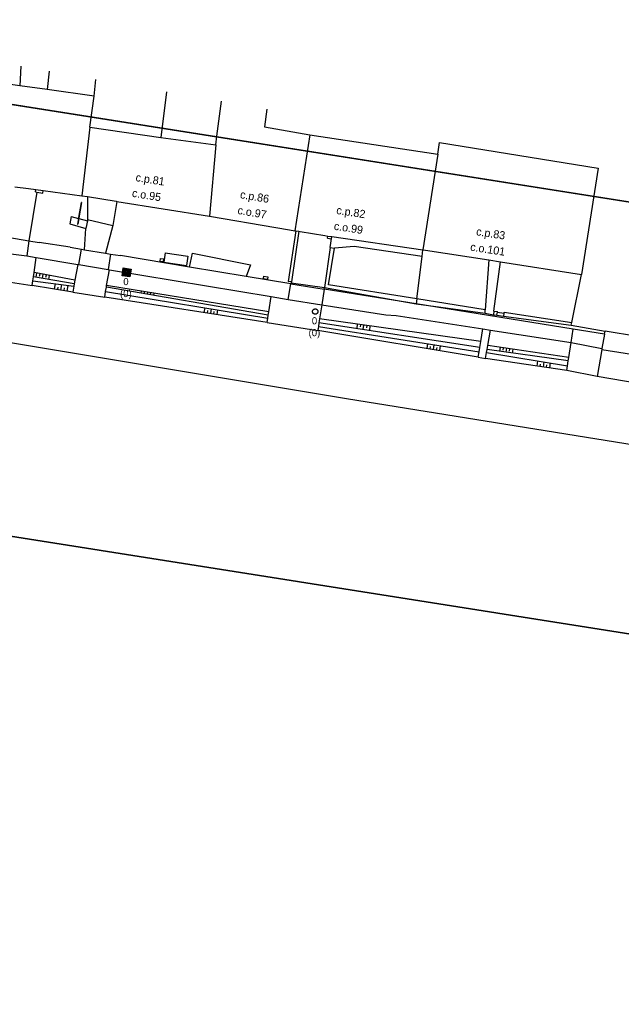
# Model space of a CAD drawing. Extents: x -594451 to -591069, y -1167621 to -1167156.
# Drawn here: x -591351.9 to -591295.5, y -1167315.7 to -1167223.5 of the extents above; entities that cross this region are included whole.
import ezdxf

# ---------------------------------------------------------------- set-up
doc = ezdxf.new("R2010")
doc.units = 0
for name, color, linetype in [('MAPA', 7, 'Continuous'), ('Uliční vpusť', 7, 'Continuous'), ('Vstupní šachta stoky', 7, 'Continuous'), ('Žádosti', 7, 'Continuous')]:
    doc.layers.add(name, color=color, linetype=linetype)

msp = doc.modelspace()

# ---------------------------------------------------------------- linework, layer by layer
at = {"layer": 'MAPA'}
for p, q in [((-591351.764, -1167227.873), (-591351.87, -1167229.7)), ((-591349.119, -1167228.334), (-591349.29, -1167230.06)), ((-591344.89, -1167230.68), (-591344.72, -1167229.1)), ((-591338.114, -1167230.25), (-591338.62, -1167234.53)), ((-591333.39, -1167234.43), (-591332.95, -1167231.149)), ((-591328.705, -1167231.889), (-591328.9, -1167233.54))]:
    msp.add_line(p, q, dxfattribs=at)
for points in [[(-591349.29, -1167230.06), (-591351.87, -1167229.7), (-591357.18, -1167228.96)], [(-591344.89, -1167230.68), (-591349.29, -1167230.06)], [(-591345.3, -1167233.59), (-591344.89, -1167230.68)], [(-591345.3, -1167233.59), (-591346.03, -1167240.01)], [(-591345.3, -1167233.59), (-591338.62, -1167234.53)], [(-591328.9, -1167233.54), (-591324.66, -1167234.28)], [(-591338.62, -1167234.53), (-591333.47, -1167235.24)], [(-591333.47, -1167235.24), (-591333.39, -1167234.43)], [(-591324.66, -1167234.28), (-591326.07, -1167243.28)], [(-591324.66, -1167234.28), (-591312.67, -1167236.1)], [(-591312.67, -1167236.1), (-591312.5, -1167235.01)], [(-591312.5, -1167235.01), (-591297.62, -1167237.41)], [(-591333.47, -1167235.24), (-591334.07, -1167241.92)], [(-591312.67, -1167236.1), (-591314.06, -1167245.06)], [(-591297.62, -1167237.41), (-591299.19, -1167247.38)], [(-591352.32, -1167239.17), (-591351.04, -1167239.34)], [(-591351.04, -1167239.34), (-591350.37, -1167239.43), (-591349.67, -1167239.52), (-591346.03, -1167240.01)], [(-591350.27, -1167239.67), (-591351.01, -1167244.23)], [(-591350.4, -1167239.65), (-591350.37, -1167239.43)], [(-591350.4, -1167239.65), (-591350.27, -1167239.67), (-591349.7, -1167239.75)], [(-591349.7, -1167239.75), (-591349.67, -1167239.52)], [(-591346.07, -1167240.64), (-591346.11, -1167240.63), (-591346.36, -1167242.05), (-591346.37, -1167242.13)], [(-591346.07, -1167240.64), (-591346.32, -1167242.06)], [(-591346.03, -1167240.01), (-591345.52, -1167240.09)], [(-591345.5, -1167240.09), (-591345.52, -1167242.23), (-591345.52, -1167242.36)], [(-591345.52, -1167240.09), (-591345.5, -1167240.09), (-591342.83, -1167240.52)], [(-591342.75, -1167240.53), (-591343.13, -1167242.79)], [(-591342.83, -1167240.52), (-591342.75, -1167240.53), (-591334.07, -1167241.92)], [(-591347.03, -1167241.95), (-591347.18, -1167242.65)], [(-591347.03, -1167241.95), (-591346.37, -1167242.13)], [(-591346.37, -1167242.13), (-591346.45, -1167242.66), (-591346.41, -1167242.67)], [(-591346.33, -1167242.14), (-591346.41, -1167242.67)], [(-591346.32, -1167242.06), (-591346.33, -1167242.14)], [(-591346.33, -1167242.14), (-591345.52, -1167242.36)], [(-591345.52, -1167242.36), (-591345.67, -1167243.07)], [(-591345.52, -1167242.23), (-591343.13, -1167242.79)], [(-591334.07, -1167241.92), (-591327.84, -1167242.98)], [(-591347.18, -1167242.65), (-591345.67, -1167243.07)], [(-591345.78, -1167245.06), (-591345.67, -1167243.07)], [(-591343.13, -1167242.79), (-591343.83, -1167245.4)], [(-591327.84, -1167242.98), (-591326.57, -1167243.19)], [(-591325.99, -1167243.29), (-591326.7, -1167248.03)], [(-591326.57, -1167243.19), (-591326.07, -1167243.28)], [(-591325.69, -1167243.34), (-591326.38, -1167248.08)], [(-591326.07, -1167243.28), (-591325.99, -1167243.29), (-591325.69, -1167243.34), (-591325.56, -1167243.36)], [(-591325.56, -1167243.36), (-591323.27, -1167243.73)], [(-591353.71, -1167243.77), (-591351.01, -1167244.23)], [(-591351.01, -1167244.23), (-591351.21, -1167245.65)], [(-591351.01, -1167244.23), (-591350.05, -1167244.39)], [(-591323.27, -1167243.73), (-591322.98, -1167243.78), (-591322.61, -1167243.84), (-591322.6, -1167243.84)], [(-591323.02, -1167243.99), (-591322.98, -1167243.78)], [(-591323.02, -1167243.99), (-591322.64, -1167244.03)], [(-591322.75, -1167244.85), (-591322.6, -1167243.84)], [(-591322.64, -1167244.03), (-591322.61, -1167243.84)], [(-591322.6, -1167243.84), (-591314.06, -1167245.06)], [(-591347.13, -1167244.84), (-591350.05, -1167244.39)], [(-591347.13, -1167244.84), (-591346.08, -1167245.01)], [(-591346.32, -1167246.46), (-591346.08, -1167245.01)], [(-591346.08, -1167245.01), (-591345.78, -1167245.06)], [(-591345.78, -1167245.06), (-591343.83, -1167245.4)], [(-591322.75, -1167244.85), (-591323.3, -1167248.62)], [(-591314.64, -1167249.67), (-591322.9, -1167248.34), (-591322.35, -1167244.92)], [(-591322.75, -1167244.85), (-591322.35, -1167244.92)], [(-591314.14, -1167245.69), (-591320.52, -1167244.75), (-591322.35, -1167244.92)], [(-591314.64, -1167249.67), (-591314.14, -1167245.69), (-591314.06, -1167245.06)], [(-591314.06, -1167245.06), (-591313.81, -1167245.1)], [(-591313.81, -1167245.1), (-591307.89, -1167246.02)], [(-591353.94, -1167245.3), (-591351.21, -1167245.65)], [(-591351.21, -1167245.65), (-591350.31, -1167245.8)], [(-591350.69, -1167248.41), (-591350.63, -1167247.99), (-591350.57, -1167247.61), (-591350.51, -1167247.21), (-591350.31, -1167245.8)], [(-591350.31, -1167245.8), (-591346.43, -1167246.44)], [(-591343.83, -1167245.4), (-591343.34, -1167245.48)], [(-591343.34, -1167245.48), (-591343.58, -1167246.92)], [(-591343.34, -1167245.48), (-591342.42, -1167245.61)], [(-591326.45, -1167248.27), (-591330.64, -1167247.57), (-591335.95, -1167246.69), (-591342.42, -1167245.61)], [(-591338.7, -1167246.13), (-591338.66, -1167245.89)], [(-591338.7, -1167246.13), (-591338.38, -1167246.18)], [(-591338.66, -1167245.89), (-591338.34, -1167245.93)], [(-591338.38, -1167246.18), (-591338.34, -1167245.93)], [(-591338.24, -1167245.36), (-591338.36, -1167246.22)], [(-591338.24, -1167245.36), (-591336.1, -1167245.67)], [(-591336.1, -1167245.67), (-591336.23, -1167246.53)], [(-591335.95, -1167246.69), (-591335.67, -1167245.39), (-591330.24, -1167246.48), (-591330.64, -1167247.57)], [(-591307.89, -1167246.02), (-591308.21, -1167250.7)], [(-591307.89, -1167246.02), (-591306.79, -1167246.19)], [(-591307.4, -1167250.82), (-591306.79, -1167246.19)], [(-591306.79, -1167246.19), (-591299.19, -1167247.38)], [(-591346.43, -1167246.44), (-591346.69, -1167247.91), (-591346.75, -1167248.25), (-591346.79, -1167248.48), (-591346.88, -1167249.03)], [(-591346.43, -1167246.44), (-591346.32, -1167246.46), (-591343.58, -1167246.92), (-591343.46, -1167246.94)], [(-591343.9, -1167249.51), (-591343.81, -1167248.98), (-591343.74, -1167248.57), (-591343.72, -1167248.43), (-591343.46, -1167246.94)], [(-591343.46, -1167246.94), (-591328.28, -1167249.46)], [(-591338.36, -1167246.22), (-591336.23, -1167246.53)], [(-591354.38, -1167247.85), (-591350.69, -1167248.41)], [(-591350.63, -1167247.99), (-591346.79, -1167248.48)], [(-591346.75, -1167248.25), (-591350.57, -1167247.61)], [(-591346.69, -1167247.91), (-591350.51, -1167247.21)], [(-591350.33, -1167247.65), (-591350.26, -1167247.26)], [(-591350, -1167247.53), (-591349.96, -1167247.31)], [(-591349.74, -1167247.75), (-591349.67, -1167247.36)], [(-591349.41, -1167247.63), (-591349.37, -1167247.42)], [(-591349.14, -1167247.85), (-591349.08, -1167247.47)], [(-591329, -1167247.53), (-591329.04, -1167247.76)], [(-591329.04, -1167247.76), (-591328.64, -1167247.83)], [(-591329, -1167247.53), (-591328.6, -1167247.6)], [(-591328.6, -1167247.6), (-591328.64, -1167247.83)], [(-591326.38, -1167248.08), (-591326.7, -1167248.03)], [(-591300.16, -1167252.14), (-591300.11, -1167251.89), (-591299.19, -1167247.38)], [(-591346.88, -1167249.03), (-591350.69, -1167248.41)], [(-591348.55, -1167248.25), (-591348.63, -1167248.74)], [(-591348.3, -1167248.57), (-591348.34, -1167248.79)], [(-591347.96, -1167248.33), (-591348.04, -1167248.84)], [(-591347.7, -1167248.65), (-591347.74, -1167248.89)], [(-591347.36, -1167248.41), (-591347.45, -1167248.94)], [(-591343.81, -1167248.98), (-591328.61, -1167251.49)], [(-591328.56, -1167251.2), (-591343.74, -1167248.57)], [(-591328.51, -1167250.89), (-591343.72, -1167248.43)], [(-591340.49, -1167249.14), (-591340.46, -1167248.96)], [(-591326.68, -1167249.73), (-591326.45, -1167248.27)], [(-591326.38, -1167248.08), (-591326.4, -1167248.16), (-591326.45, -1167248.27)], [(-591326.45, -1167248.27), (-591323.31, -1167248.76)], [(-591326.4, -1167248.16), (-591323.3, -1167248.62)], [(-591323.31, -1167248.76), (-591323.54, -1167250.22)], [(-591323.31, -1167248.76), (-591323.3, -1167248.62)], [(-591297.02, -1167252.99), (-591299.96, -1167252.52), (-591314.7, -1167250.14), (-591323.31, -1167248.76)], [(-591323.3, -1167248.62), (-591314.7, -1167250.14)], [(-591346.88, -1167249.03), (-591343.9, -1167249.51)], [(-591328.67, -1167251.89), (-591343.9, -1167249.51)], [(-591340.18, -1167249.09), (-591340.16, -1167249.01)], [(-591339.9, -1167249.24), (-591339.87, -1167249.05)], [(-591339.59, -1167249.2), (-591339.57, -1167249.1)], [(-591339.3, -1167249.34), (-591339.27, -1167249.15)], [(-591328.67, -1167251.89), (-591328.61, -1167251.49), (-591328.56, -1167251.2), (-591328.51, -1167250.89), (-591328.28, -1167249.46)], [(-591328.28, -1167249.46), (-591326.68, -1167249.73)], [(-591326.68, -1167249.73), (-591323.54, -1167250.22)], [(-591314.64, -1167249.67), (-591314.7, -1167250.14)], [(-591308.21, -1167250.7), (-591314.64, -1167249.67)], [(-591334.51, -1167250.51), (-591334.59, -1167250.95)], [(-591334.25, -1167250.77), (-591334.29, -1167251)], [(-591333.92, -1167250.61), (-591333.99, -1167251.05)], [(-591333.33, -1167250.71), (-591333.4, -1167251.14)], [(-591323.54, -1167250.22), (-591323.75, -1167251.54), (-591323.81, -1167251.91), (-591323.86, -1167252.25), (-591323.92, -1167252.63)], [(-591323.54, -1167250.22), (-591317.53, -1167251.17)], [(-591314.7, -1167250.14), (-591308.23, -1167251.02)], [(-591308.23, -1167251.02), (-591308.21, -1167250.7)], [(-591307.4, -1167250.82), (-591307.45, -1167251.16)], [(-591307.4, -1167250.82), (-591307.06, -1167250.85)], [(-591333.66, -1167250.85), (-591333.7, -1167251.1)], [(-591308.63, -1167253.68), (-591323.75, -1167251.54)], [(-591317.53, -1167251.17), (-591316.58, -1167251.23)], [(-591316.58, -1167251.23), (-591308.43, -1167252.49)], [(-591308.23, -1167251.02), (-591307.45, -1167251.16)], [(-591307.45, -1167251.16), (-591307.12, -1167251.2)], [(-591307.12, -1167251.2), (-591307.07, -1167250.91), (-591306.46, -1167251)], [(-591307.12, -1167251.2), (-591306.51, -1167251.28)], [(-591307.07, -1167250.91), (-591307.06, -1167250.85)], [(-591306.46, -1167251), (-591306.51, -1167251.28)], [(-591306.51, -1167251.28), (-591300.16, -1167252.14)], [(-591306.46, -1167251), (-591306.45, -1167250.93)], [(-591306.45, -1167250.93), (-591300.11, -1167251.89)], [(-591328.67, -1167251.89), (-591323.92, -1167252.63)], [(-591308.88, -1167255.12), (-591323.92, -1167252.63)], [(-591323.86, -1167252.25), (-591308.8, -1167254.65)], [(-591308.72, -1167254.22), (-591323.81, -1167251.91)], [(-591320.24, -1167252.46), (-591320.18, -1167252.04)], [(-591319.92, -1167252.3), (-591319.89, -1167252.09)], [(-591319.65, -1167252.55), (-591319.59, -1167252.13)], [(-591319.32, -1167252.39), (-591319.29, -1167252.17)], [(-591319.05, -1167252.64), (-591319, -1167252.21)], [(-591308.88, -1167255.12), (-591308.8, -1167254.65), (-591308.72, -1167254.22), (-591308.63, -1167253.68), (-591308.43, -1167252.49)], [(-591308.43, -1167252.49), (-591307.73, -1167252.6)], [(-591308.19, -1167255.26), (-591308.09, -1167254.69), (-591308.05, -1167254.43), (-591307.98, -1167254.03), (-591307.73, -1167252.6)], [(-591307.73, -1167252.6), (-591300.17, -1167253.77)], [(-591300.17, -1167253.77), (-591299.96, -1167252.52)], [(-591300.16, -1167252.14), (-591296.98, -1167252.69)], [(-591357.63, -1167252.95), (-591321.23, -1167259.02), (-591254.866, -1167269.682), (-591254.389, -1167269.757), (-591238.78, -1167272.23)], [(-591297.02, -1167252.99), (-591297.27, -1167254.32), (-591297.29, -1167254.42)], [(-591297.02, -1167252.99), (-591296.98, -1167252.69)], [(-591293.93, -1167253.2), (-591296.98, -1167252.69)], [(-591313.63, -1167253.88), (-591313.7, -1167254.32)], [(-591313.37, -1167254.15), (-591313.4, -1167254.37)], [(-591313.03, -1167253.98), (-591313.11, -1167254.42)], [(-591312.77, -1167254.23), (-591312.81, -1167254.47)], [(-591312.44, -1167254.07), (-591312.52, -1167254.52)], [(-591300.43, -1167255.48), (-591308.05, -1167254.43)], [(-591300.38, -1167255.17), (-591307.98, -1167254.03)], [(-591306.85, -1167254.6), (-591306.79, -1167254.21)], [(-591306.53, -1167254.47), (-591306.5, -1167254.26)], [(-591306.26, -1167254.68), (-591306.2, -1167254.3)], [(-591305.94, -1167254.56), (-591305.9, -1167254.34)], [(-591305.66, -1167254.76), (-591305.61, -1167254.39)], [(-591300.57, -1167256.38), (-591300.5, -1167255.94), (-591300.43, -1167255.48), (-591300.38, -1167255.17), (-591300.17, -1167253.77)], [(-591300.17, -1167253.77), (-591297.27, -1167254.32)], [(-591297.29, -1167254.42), (-591297.72, -1167256.94)], [(-591297.29, -1167254.42), (-591282.36, -1167256.75)], [(-591308.88, -1167255.12), (-591308.19, -1167255.26)], [(-591300.57, -1167256.38), (-591308.19, -1167255.26)], [(-591308.09, -1167254.69), (-591300.5, -1167255.94)], [(-591303.31, -1167255.48), (-591303.39, -1167255.97)], [(-591303.06, -1167255.79), (-591303.09, -1167256.01)], [(-591302.72, -1167255.57), (-591302.79, -1167256.06)], [(-591302.46, -1167255.86), (-591302.5, -1167256.1)], [(-591302.13, -1167255.67), (-591302.2, -1167256.14)], [(-591297.72, -1167256.94), (-591300.57, -1167256.38)], [(-591237.5, -1167266.94), (-591282.92, -1167259.49), (-591297.72, -1167256.94)]]:
    msp.add_lwpolyline(points, dxfattribs=at)
at = {"layer": 'Uliční vpusť'}
for points in [[(-591341.528, -1167247.619), (-591342.269, -1167247.502), (-591342.152, -1167246.761), (-591341.411, -1167246.878)], [(-591341.509, -1167247.212), (-591342.161, -1167247.109), (-591342.152, -1167247.049), (-591341.5, -1167247.153)], [(-591341.491, -1167247.093), (-591342.142, -1167246.99), (-591342.133, -1167246.931), (-591341.481, -1167247.034)], [(-591341.472, -1167246.975), (-591342.124, -1167246.872), (-591342.114, -1167246.812), (-591341.462, -1167246.916)], [(-591341.566, -1167247.568), (-591342.218, -1167247.464), (-591342.208, -1167247.405), (-591341.556, -1167247.508)], [(-591341.547, -1167247.449), (-591342.199, -1167247.346), (-591342.189, -1167247.287), (-591341.538, -1167247.39)], [(-591341.528, -1167247.331), (-591342.18, -1167247.227), (-591342.171, -1167247.168), (-591341.519, -1167247.271)]]:
    msp.add_lwpolyline(points, close=True, dxfattribs=at)
at = {"layer": 'Vstupní šachta stoky'}
msp.add_line((-591324.173, -1167250.61), (-591324.16, -1167250.61), dxfattribs=at)
for points in [[(-591324.16, -1167250.61), (-591324.147, -1167250.61), (-591324.134, -1167250.611), (-591324.121, -1167250.613), (-591324.108, -1167250.616), (-591324.095, -1167250.619), (-591324.082, -1167250.622), (-591324.07, -1167250.627), (-591324.058, -1167250.632), (-591324.046, -1167250.638), (-591324.034, -1167250.644), (-591324.023, -1167250.651), (-591324.012, -1167250.659), (-591324.002, -1167250.667), (-591323.992, -1167250.675), (-591323.982, -1167250.684), (-591323.973, -1167250.694), (-591323.965, -1167250.704), (-591323.957, -1167250.715), (-591323.949, -1167250.726), (-591323.942, -1167250.737), (-591323.936, -1167250.749), (-591323.931, -1167250.761), (-591323.926, -1167250.773), (-591323.921, -1167250.785), (-591323.918, -1167250.798), (-591323.915, -1167250.811), (-591323.913, -1167250.824), (-591323.911, -1167250.837), (-591323.91, -1167250.85), (-591323.91, -1167250.863), (-591323.911, -1167250.877), (-591323.912, -1167250.89), (-591323.914, -1167250.903), (-591323.916, -1167250.916), (-591323.92, -1167250.928), (-591323.923, -1167250.941), (-591323.928, -1167250.953), (-591323.933, -1167250.966), (-591323.939, -1167250.977), (-591323.946, -1167250.989), (-591323.953, -1167251), (-591323.96, -1167251.011), (-591323.969, -1167251.021), (-591323.977, -1167251.031), (-591323.987, -1167251.04), (-591323.997, -1167251.049), (-591324.007, -1167251.058), (-591324.017, -1167251.065), (-591324.028, -1167251.073), (-591324.04, -1167251.079), (-591324.052, -1167251.085), (-591324.064, -1167251.091), (-591324.076, -1167251.095), (-591324.088, -1167251.1), (-591324.101, -1167251.103), (-591324.114, -1167251.106), (-591324.127, -1167251.108), (-591324.14, -1167251.109), (-591324.153, -1167251.11), (-591324.167, -1167251.11), (-591324.18, -1167251.109), (-591324.193, -1167251.108), (-591324.206, -1167251.106), (-591324.219, -1167251.103), (-591324.232, -1167251.1), (-591324.244, -1167251.095), (-591324.256, -1167251.091), (-591324.268, -1167251.085), (-591324.28, -1167251.079), (-591324.292, -1167251.073), (-591324.303, -1167251.065), (-591324.313, -1167251.058), (-591324.323, -1167251.049), (-591324.333, -1167251.04), (-591324.343, -1167251.031), (-591324.351, -1167251.021), (-591324.36, -1167251.011), (-591324.367, -1167251), (-591324.374, -1167250.989), (-591324.381, -1167250.977), (-591324.387, -1167250.966), (-591324.392, -1167250.953), (-591324.397, -1167250.941), (-591324.4, -1167250.928), (-591324.404, -1167250.916), (-591324.406, -1167250.903), (-591324.408, -1167250.89), (-591324.409, -1167250.877), (-591324.41, -1167250.863), (-591324.41, -1167250.85), (-591324.409, -1167250.837), (-591324.407, -1167250.824), (-591324.405, -1167250.811), (-591324.402, -1167250.798), (-591324.399, -1167250.785), (-591324.394, -1167250.773), (-591324.389, -1167250.761), (-591324.384, -1167250.749), (-591324.378, -1167250.737), (-591324.371, -1167250.726)], [(-591324.371, -1167250.726), (-591324.363, -1167250.715), (-591324.355, -1167250.704), (-591324.347, -1167250.694), (-591324.338, -1167250.684), (-591324.328, -1167250.675), (-591324.318, -1167250.667), (-591324.308, -1167250.659), (-591324.297, -1167250.651), (-591324.286, -1167250.644), (-591324.274, -1167250.638), (-591324.262, -1167250.632), (-591324.25, -1167250.627), (-591324.238, -1167250.622), (-591324.225, -1167250.619), (-591324.212, -1167250.616), (-591324.199, -1167250.613), (-591324.186, -1167250.611), (-591324.173, -1167250.61)]]:
    msp.add_lwpolyline(points, dxfattribs=at)
at = {"layer": 'Žádosti'}
for points in [[(-591075.541, -1167315.702), (-591409.141, -1167263.011), (-591402.9, -1167223.501), (-591277.812, -1167243.258), (-591238.702, -1167227.393), (-591201.747, -1167234.05), (-591163.587, -1167259.868), (-591069.3, -1167276.192)], [(-591402.829, -1167223.512), (-591405.554, -1167240.302), (-591409.141, -1167263.011), (-591075.541, -1167315.702), (-591069.3, -1167276.192), (-591163.587, -1167259.868), (-591201.747, -1167234.05), (-591238.702, -1167227.393), (-591277.812, -1167243.258)]]:
    msp.add_lwpolyline(points, close=True, dxfattribs=at)

# ---------------------------------------------------------------- texts
at = {"layer": 'MAPA'}
for s, rotation, p in [('c.p.81', 350.88053, (-591341.039, -1167238.628)), ('c.o.95', 350.88053, (-591341.379, -1167240.094)), ('c.p.86', 350.35777, (-591331.247, -1167240.227)), ('c.o.97', 350.35777, (-591331.48, -1167241.706)), ('c.p.82', 351.27998, (-591322.217, -1167241.703)), ('c.o.99', 351.27998, (-591322.446, -1167243.184)), ('c.p.83', 351.33835, (-591309.106, -1167243.701)), ('c.o.101', 351.33835, (-591309.661, -1167245.14))]:
    msp.add_text(s, height=0.75, rotation=rotation, dxfattribs=at).set_placement(p)
at = {"layer": 'Uliční vpusť'}
for s, height, p in [('0', 0.671, (-591342.156, -1167248.386)), ('(0)', 0.6708, (-591342.462, -1167249.504))]:
    msp.add_text(s, height=height, dxfattribs=at).set_placement(p)
msp.add_text('Rozhodnout', height=0.0578, rotation=170.99539, dxfattribs=at).set_placement((-591341.581, -1167247.227))
at = {"layer": 'Vstupní šachta stoky'}
for s, height, p in [('0', 0.671, (-591324.476, -1167252.056)), ('(0)', 0.6708, (-591324.782, -1167253.174))]:
    msp.add_text(s, height=height, dxfattribs=at).set_placement(p)

doc.saveas('drawing.dxf')
